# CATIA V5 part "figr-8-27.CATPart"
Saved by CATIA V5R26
Part number: Part2
Bounding box of the stored display mesh (mm): x -50 to 500, y -650 to 50, z 0 to 50
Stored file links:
  D:\_Deepak\CATIA\CATIA V5-6R2016_Deepak\Resources\Part files\Partfiles\c08_catia_v5_6r2016_prt\figr-8-27.CATPart
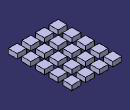
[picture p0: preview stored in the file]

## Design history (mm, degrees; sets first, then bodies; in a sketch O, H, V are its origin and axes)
Body1 (main body)
  Sketch1 on xy-plane, origin (0, 0, 0), H (1, 0, 0), V (0, 1, 0)
    line L1 (-50, 50) -> (50, 50)
    line L2 (50, 50) -> (50, -50)
    line L3 (50, -50) -> (-50, -50)
    line L4 (-50, -50) -> (-50, 50)
    axis line L5 (50, -50) -> (-50, 50)
    length L3 = 100
    length L2 = 100
    horizontal: L1 H, L3 H
    vertical: L2 V, L4 V
    midpoint: O L5
  Pad1: profile Sketch1, direction (0, 0, 1), length 50
  RectPattern1: of the body so far, direction 1 instances 4, spacing 150, along edge [face of Pad1 | face of Pad1], direction 2 instances 5, spacing 150, along edge [face of Pad1 | face of Pad1]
